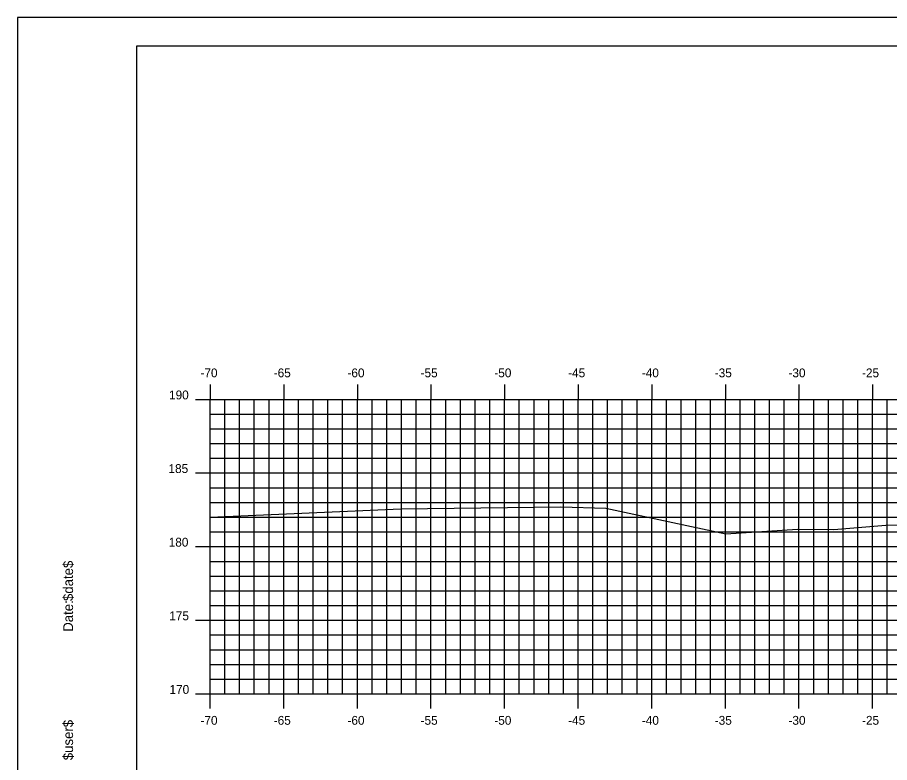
# Model space of a CAD drawing. Extents: x 1139872 to 1140042, y 608981 to 609091.
# Drawn here: x 1139871.9 to 1139931.1, y 609040.7 to 609091.3 of the extents above; entities that cross this region are included whole.
import ezdxf

# ---------------------------------------------------------------- set-up
doc = ezdxf.new("R2010")
doc.units = 0
for name, color, linetype in [('BORDER', 7, 'Continuous'), ('H_V ANNOTATION', 7, 'Continuous'), ('MAJOR', 7, 'Continuous'), ('MINOR', 7, 'Continuous'), ('PLOT BOUNDARY', 7, 'Continuous'), ('S_Roadway_Centerline', 7, 'Continuous')]:
    doc.layers.add(name, color=color, linetype=linetype)

msp = doc.modelspace()

# ---------------------------------------------------------------- linework, layer by layer
at = {"layer": 'BORDER'}
msp.add_lwpolyline([(1139879.975, 608984.335), (1140039.975, 608984.335), (1140039.975, 609089.335), (1139879.975, 609089.335)], close=True, dxfattribs=at)
at = {"layer": 'MAJOR'}
for p, q in [((1139884.975, 609066.337), (1139884.975, 609065.335)), ((1139889.975, 609066.337), (1139889.975, 609065.335)), ((1139894.975, 609066.337), (1139894.975, 609065.335)), ((1139899.975, 609066.337), (1139899.975, 609065.335)), ((1139904.975, 609066.337), (1139904.975, 609065.335)), ((1139909.975, 609066.337), (1139909.975, 609065.335)), ((1139914.975, 609066.337), (1139914.975, 609065.335)), ((1139919.975, 609066.337), (1139919.975, 609065.335)), ((1139924.975, 609066.337), (1139924.975, 609065.335)), ((1139929.975, 609066.337), (1139929.975, 609065.335)), ((1139883.973, 609065.335), (1139884.975, 609065.335)), ((1139884.975, 609065.335), (1140024.975, 609065.335)), ((1139884.975, 609045.335), (1139884.975, 609065.335)), ((1139884.975, 609045.335), (1139884.975, 609065.335)), ((1139884.975, 609065.335), (1140024.975, 609065.335)), ((1139889.975, 609045.335), (1139889.975, 609065.335)), ((1139894.975, 609045.335), (1139894.975, 609065.335)), ((1139899.975, 609045.335), (1139899.975, 609065.335)), ((1139904.975, 609045.335), (1139904.975, 609065.335)), ((1139909.975, 609045.335), (1139909.975, 609065.335)), ((1139914.975, 609045.335), (1139914.975, 609065.335)), ((1139919.975, 609045.335), (1139919.975, 609065.335)), ((1139924.975, 609045.335), (1139924.975, 609065.335)), ((1139929.975, 609045.335), (1139929.975, 609065.335)), ((1139883.973, 609060.335), (1139884.975, 609060.335)), ((1139884.975, 609060.335), (1140024.975, 609060.335)), ((1139883.973, 609055.335), (1139884.975, 609055.335)), ((1139884.975, 609055.335), (1140024.975, 609055.335)), ((1139883.973, 609050.335), (1139884.975, 609050.335)), ((1139884.975, 609050.335), (1140024.975, 609050.335)), ((1139883.973, 609045.335), (1139884.975, 609045.335)), ((1139884.975, 609045.335), (1140024.975, 609045.335)), ((1139884.975, 609045.335), (1140024.975, 609045.335)), ((1139884.975, 609044.333), (1139884.975, 609045.335)), ((1139889.975, 609044.333), (1139889.975, 609045.335)), ((1139894.975, 609044.333), (1139894.975, 609045.335)), ((1139899.975, 609044.333), (1139899.975, 609045.335)), ((1139904.975, 609044.333), (1139904.975, 609045.335)), ((1139909.975, 609044.333), (1139909.975, 609045.335)), ((1139914.975, 609044.333), (1139914.975, 609045.335)), ((1139919.975, 609044.333), (1139919.975, 609045.335)), ((1139924.975, 609044.333), (1139924.975, 609045.335)), ((1139929.975, 609044.333), (1139929.975, 609045.335))]:
    msp.add_line(p, q, dxfattribs=at)
at = {"layer": 'MINOR'}
for p, q in [((1139885.975, 609045.335), (1139885.975, 609065.335)), ((1139886.975, 609045.335), (1139886.975, 609065.335)), ((1139887.975, 609045.335), (1139887.975, 609065.335)), ((1139888.975, 609045.335), (1139888.975, 609065.335)), ((1139890.975, 609045.335), (1139890.975, 609065.335)), ((1139891.975, 609045.335), (1139891.975, 609065.335)), ((1139892.975, 609045.335), (1139892.975, 609065.335)), ((1139893.975, 609045.335), (1139893.975, 609065.335)), ((1139895.975, 609045.335), (1139895.975, 609065.335)), ((1139896.975, 609045.335), (1139896.975, 609065.335)), ((1139897.975, 609045.335), (1139897.975, 609065.335)), ((1139898.975, 609045.335), (1139898.975, 609065.335)), ((1139900.975, 609045.335), (1139900.975, 609065.335)), ((1139901.975, 609045.335), (1139901.975, 609065.335)), ((1139902.975, 609045.335), (1139902.975, 609065.335)), ((1139903.975, 609045.335), (1139903.975, 609065.335)), ((1139905.975, 609045.335), (1139905.975, 609065.335)), ((1139906.975, 609045.335), (1139906.975, 609065.335)), ((1139907.975, 609045.335), (1139907.975, 609065.335)), ((1139908.975, 609045.335), (1139908.975, 609065.335)), ((1139910.975, 609045.335), (1139910.975, 609065.335)), ((1139911.975, 609045.335), (1139911.975, 609065.335)), ((1139912.975, 609045.335), (1139912.975, 609065.335)), ((1139913.975, 609045.335), (1139913.975, 609065.335)), ((1139915.975, 609045.335), (1139915.975, 609065.335)), ((1139916.975, 609045.335), (1139916.975, 609065.335)), ((1139917.975, 609045.335), (1139917.975, 609065.335)), ((1139918.975, 609045.335), (1139918.975, 609065.335)), ((1139920.975, 609045.335), (1139920.975, 609065.335)), ((1139921.975, 609045.335), (1139921.975, 609065.335)), ((1139922.975, 609045.335), (1139922.975, 609065.335)), ((1139923.975, 609045.335), (1139923.975, 609065.335)), ((1139925.975, 609045.335), (1139925.975, 609065.335)), ((1139926.975, 609045.335), (1139926.975, 609065.335)), ((1139927.975, 609045.335), (1139927.975, 609065.335)), ((1139928.975, 609045.335), (1139928.975, 609065.335)), ((1139930.975, 609045.335), (1139930.975, 609065.335)), ((1139884.975, 609064.335), (1140024.975, 609064.335)), ((1139884.975, 609064.335), (1139885.977, 609064.335)), ((1139884.975, 609063.335), (1140024.975, 609063.335)), ((1139884.975, 609063.335), (1139885.977, 609063.335)), ((1139884.975, 609062.335), (1140024.975, 609062.335)), ((1139884.975, 609062.335), (1139885.977, 609062.335)), ((1139884.975, 609061.335), (1140024.975, 609061.335)), ((1139884.975, 609061.335), (1139885.977, 609061.335)), ((1139884.975, 609059.335), (1140024.975, 609059.335)), ((1139884.975, 609059.335), (1139885.977, 609059.335)), ((1139884.975, 609058.335), (1140024.975, 609058.335)), ((1139884.975, 609058.335), (1139885.977, 609058.335)), ((1139884.975, 609057.335), (1140024.975, 609057.335)), ((1139884.975, 609057.335), (1139885.977, 609057.335)), ((1139884.975, 609056.335), (1140024.975, 609056.335)), ((1139884.975, 609056.335), (1139885.977, 609056.335)), ((1139884.975, 609054.335), (1140024.975, 609054.335)), ((1139884.975, 609054.335), (1139885.977, 609054.335)), ((1139884.975, 609053.335), (1140024.975, 609053.335)), ((1139884.975, 609053.335), (1139885.977, 609053.335)), ((1139884.975, 609052.335), (1140024.975, 609052.335)), ((1139884.975, 609052.335), (1139885.977, 609052.335)), ((1139884.975, 609051.335), (1140024.975, 609051.335)), ((1139884.975, 609051.335), (1139885.977, 609051.335)), ((1139884.975, 609049.335), (1140024.975, 609049.335)), ((1139884.975, 609049.335), (1139885.977, 609049.335)), ((1139884.975, 609048.335), (1140024.975, 609048.335)), ((1139884.975, 609048.335), (1139885.977, 609048.335)), ((1139884.975, 609047.335), (1140024.975, 609047.335)), ((1139884.975, 609047.335), (1139885.977, 609047.335)), ((1139884.975, 609046.335), (1140024.975, 609046.335)), ((1139884.975, 609046.335), (1139885.977, 609046.335))]:
    msp.add_line(p, q, dxfattribs=at)
at = {"layer": 'PLOT BOUNDARY'}
msp.add_lwpolyline([(1139871.882, 608981.276), (1140041.882, 608981.276), (1140041.882, 609091.276), (1139871.882, 609091.276)], close=True, dxfattribs=at)
at = {"layer": 'S_Roadway_Centerline'}
msp.add_lwpolyline([(1139884.975, 609057.342), (1139897.918, 609057.894), (1139908.791, 609058.038), (1139911.865, 609057.935), (1139920.011, 609056.197), (1139924.881, 609056.527), (1139927.341, 609056.502), (1139930.884, 609056.791), (1139931.658, 609056.822)], dxfattribs=at)

# ---------------------------------------------------------------- texts
at = {"layer": 'BORDER'}
for s, p in [('$date$', (1139875.66, 609051.64)), ('Date:', (1139875.66, 609049.552)), ('$user$', (1139875.66, 609040.827))]:
    msp.add_text(s, height=0.6696, rotation=90, dxfattribs=at).set_placement(p)
at = {"layer": 'H_V ANNOTATION'}
for s, p in [('-70', (1139884.316, 609066.835)), ('-65', (1139889.293, 609066.835)), ('-60', (1139894.301, 609066.835)), ('-55', (1139899.271, 609066.835)), ('-50', (1139904.279, 609066.835)), ('-45', (1139909.293, 609066.835)), ('-40', (1139914.301, 609066.835)), ('-35', (1139919.255, 609066.835)), ('-30', (1139924.263, 609066.835)), ('-25', (1139929.26, 609066.835)), ('190', (1139882.18, 609065.335)), ('185', (1139882.142, 609060.335)), ('180', (1139882.158, 609055.335)), ('175', (1139882.196, 609050.335)), ('170', (1139882.212, 609045.335)), ('-70', (1139884.316, 609043.235)), ('-65', (1139889.293, 609043.235)), ('-60', (1139894.301, 609043.235)), ('-55', (1139899.271, 609043.235)), ('-50', (1139904.279, 609043.235)), ('-45', (1139909.293, 609043.235)), ('-40', (1139914.301, 609043.235)), ('-35', (1139919.255, 609043.235)), ('-30', (1139924.263, 609043.235)), ('-25', (1139929.26, 609043.235))]:
    msp.add_text(s, height=0.6, dxfattribs=at).set_placement(p)
at = {"layer": 'MAJOR'}
msp.add_text('-', height=0.006, dxfattribs=at).set_placement((1139884.97, 609045.335))

doc.saveas('drawing.dxf')
